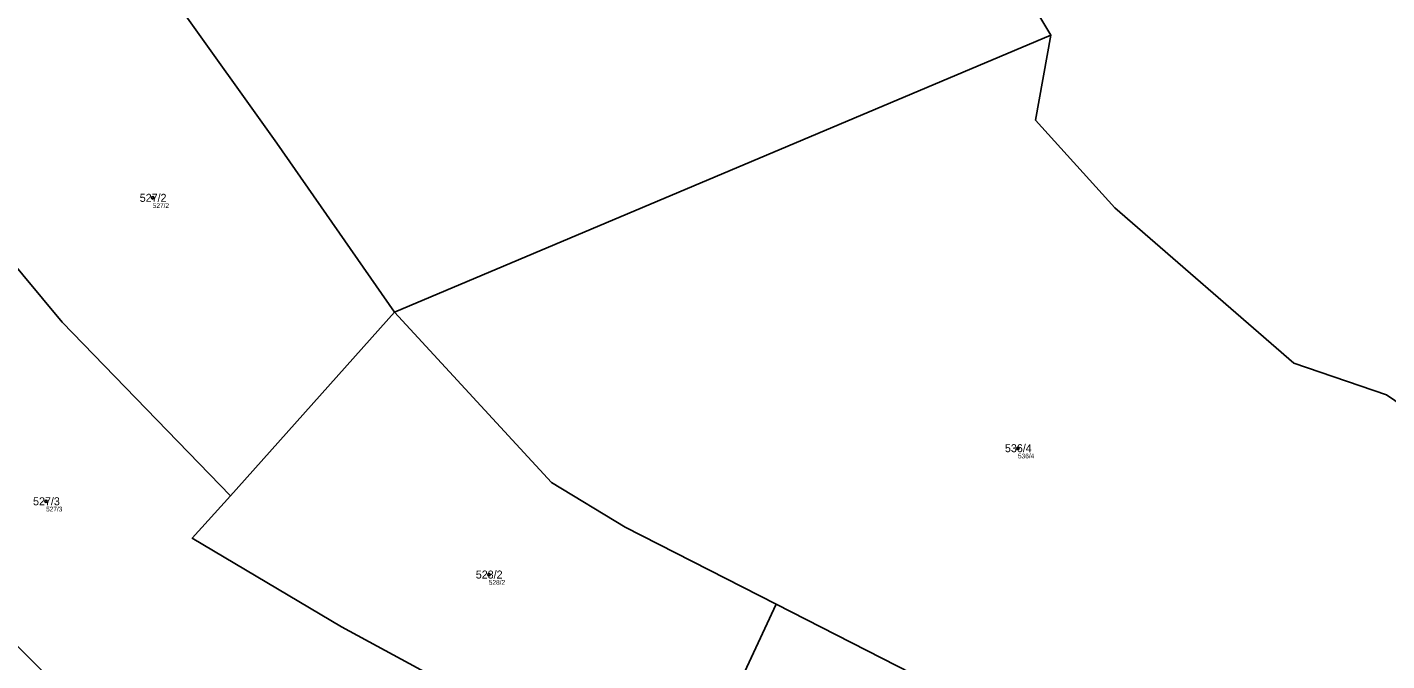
# Model space of a CAD drawing. Extents: x -766177 to -763254, y -1057727 to -1053915.
# Drawn here: x -765482.3 to -765193.5, y -1055854.6 to -1055720 of the extents above; entities that cross this region are included whole.
import ezdxf

# ---------------------------------------------------------------- set-up
doc = ezdxf.new("R2010")
doc.units = 0
for name, color, linetype in [('Vrstva 1', 7, 'Continuous'), ('Vrstva 2', 7, 'Continuous'), ('Vrstva 50', 7, 'Continuous'), ('Vrstva 51', 7, 'Continuous')]:
    doc.layers.add(name, color=color, linetype=linetype)

msp = doc.modelspace()

# ---------------------------------------------------------------- linework, layer by layer
at = {"layer": 'Vrstva 1'}
for p, q in [((-765404.25, -1055780.54), (-765264.86, -1055721.68)), ((-765439.15, -1055819.54), (-765404.25, -1055780.54)), ((-765341.92, -1055882.75), (-765323.19, -1055842.61))]:
    msp.add_line(p, q, dxfattribs=at)
for points in [[(-765264.86, -1055721.68), (-765274.26, -1055705.93), (-765299.72, -1055679.35), (-765330.25, -1055633.77), (-765347.91, -1055611.72)], [(-765404.25, -1055780.54), (-765429.26, -1055744.62), (-765450.41, -1055715.1), (-765471.72, -1055690.37)], [(-765183.17, -1055805.17), (-765193.58, -1055798.13), (-765213.25, -1055791.38), (-765251.27, -1055758.36), (-765268.1, -1055739.73), (-765264.86, -1055721.68)], [(-765519.35, -1055727.69), (-765495.84, -1055757.52), (-765474.85, -1055782.63), (-765439.15, -1055819.54)], [(-765558.59, -1055756.64), (-765515.89, -1055820.16), (-765458.01, -1055877.76), (-765390.75, -1055905.5)], [(-765323.19, -1055842.61), (-765355.29, -1055826.23), (-765370.91, -1055816.73), (-765404.25, -1055780.54)], [(-765395.3, -1055858.4), (-765415.56, -1055847.37), (-765447.23, -1055828.57), (-765439.15, -1055819.54)], [(-765264.85, -1055871.85), (-765291.21, -1055858.93), (-765323.19, -1055842.61)]]:
    msp.add_lwpolyline(points, dxfattribs=at)
at = {"layer": 'Vrstva 50'}
for centre in [(-765455.63, -1055756.22994), (-765271.83, -1055809.43994), (-765478.29, -1055820.71994), (-765384.24, -1055836.28994)]:
    msp.add_circle(centre, 0.25, dxfattribs=at)
at = {"layer": 'Vrstva 51'}
for points in [[(-765274.26, -1055705.93), (-765299.72, -1055679.35), (-765330.25, -1055633.77), (-765347.91, -1055611.72), (-765471.72, -1055690.37), (-765450.41, -1055715.1), (-765429.26, -1055744.62), (-765404.25, -1055780.54), (-765264.86, -1055721.68)], [(-765404.25, -1055780.54), (-765429.26, -1055744.62), (-765450.41, -1055715.1), (-765471.72, -1055690.37), (-765519.35, -1055727.69), (-765495.84, -1055757.52), (-765474.85, -1055782.63), (-765439.15, -1055819.54)], [(-765183.17, -1055805.17), (-765193.58, -1055798.13), (-765213.25, -1055791.38), (-765251.27, -1055758.36), (-765268.1, -1055739.73), (-765264.86, -1055721.68), (-765404.25, -1055780.54), (-765370.91, -1055816.73), (-765355.29, -1055826.23), (-765323.19, -1055842.61), (-765291.21, -1055858.93), (-765264.85, -1055871.85), (-765185.69, -1055867.77), (-765186.39, -1055862.24), (-765178.85, -1055808.22), (-765180.1, -1055807.34), (-765182.51, -1055807.92)], [(-765515.89, -1055820.16), (-765458.01, -1055877.76), (-765390.75, -1055905.5), (-765395.3, -1055858.4), (-765415.56, -1055847.37), (-765447.23, -1055828.57), (-765439.15, -1055819.54), (-765474.85, -1055782.63), (-765495.84, -1055757.52), (-765519.35, -1055727.69), (-765544.89, -1055748.79), (-765558.59, -1055756.64)], [(-765390.71, -1055936.08), (-765389.47, -1055918.75), (-765390.75, -1055905.5), (-765458.01, -1055877.76), (-765515.89, -1055820.16), (-765558.59, -1055756.64), (-765563.73, -1055759.58), (-765568.42, -1055774.3), (-765570.37, -1055780.59), (-765527.97, -1055845.59), (-765496.53, -1055876.8), (-765468.24, -1055896.12), (-765424.32, -1055922.1)], [(-765370.91, -1055816.73), (-765404.25, -1055780.54), (-765439.15, -1055819.54), (-765447.23, -1055828.57), (-765415.56, -1055847.37), (-765395.3, -1055858.4), (-765390.46, -1055861), (-765341.92, -1055882.75), (-765323.19, -1055842.61), (-765355.29, -1055826.23)], [(-765264.85, -1055871.85), (-765291.21, -1055858.93), (-765323.19, -1055842.61), (-765341.92, -1055882.75), (-765326.64, -1055889.6), (-765276.96, -1055906.31)]]:
    msp.add_lwpolyline(points, close=True, dxfattribs=at)
msp.add_lwpolyline([(-765274.26, -1055705.93), (-765264.86, -1055721.68), (-765268.1, -1055739.73), (-765251.27, -1055758.36), (-765213.25, -1055791.38), (-765193.58, -1055798.13), (-765183.17, -1055805.17), (-765183.59, -1055803.44), (-765179.89, -1055802.56), (-765180.2, -1055801.29), (-765177.67, -1055800.68), (-765177.36, -1055801.95), (-765173.67, -1055801.06), (-765173.44, -1055802.03), (-765172.07, -1055801.71), (-765171.47, -1055804.23), (-765172.83, -1055804.56), (-765172.59, -1055805.53), (-765180.1, -1055807.34), (-765178.85, -1055808.22), (-765137.25, -1055797.05), (-765129.73, -1055795.01), (-765172.52, -1055723.1), (-765211.24, -1055668.61)], dxfattribs=at)

# ---------------------------------------------------------------- texts
at = {"layer": 'Vrstva 2'}
for s, p in [('527/2', (-765458.403, -1055757.08)), ('536/4', (-765274.603, -1055810.29)), ('527/3', (-765481.063, -1055821.57)), ('528/2', (-765387.013, -1055837.14))]:
    msp.add_text(s, height=1.699998, dxfattribs=at).set_placement(p)
at = {"layer": 'Vrstva 50'}
for s, p in [('527/2', (-765455.63, -1055758.386)), ('536/4', (-765271.83, -1055811.596)), ('527/3', (-765478.29, -1055822.876)), ('528/2', (-765384.24, -1055838.446))]:
    msp.add_text(s, height=0.999996, dxfattribs=at).set_placement(p)

doc.saveas('drawing.dxf')
